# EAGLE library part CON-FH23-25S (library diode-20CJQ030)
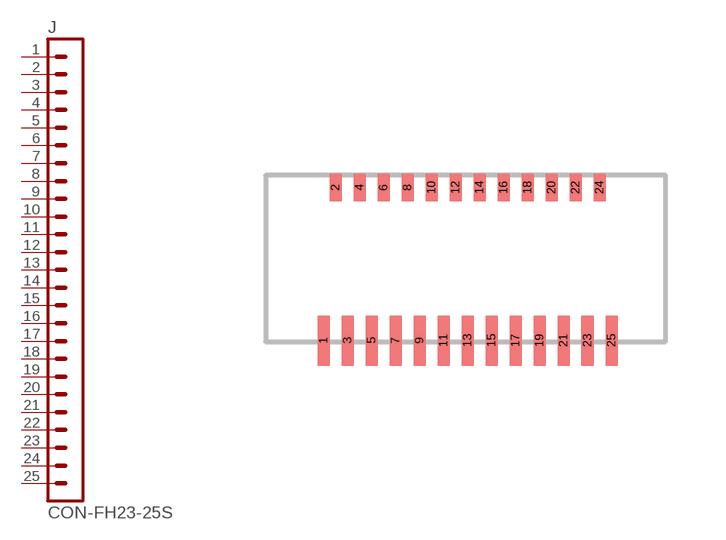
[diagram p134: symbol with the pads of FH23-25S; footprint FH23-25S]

Designator prefix J

## CON-FH23-25S  [FH23-25S]
1  1  pas
2  2  pas
3  3  pas
4  4  pas
5  5  pas
6  6  pas
7  7  pas
8  8  pas
9  9  pas
10  10  pas
11  11  pas
12  12  pas
13  13  pas
14  14  pas
15  15  pas
16  16  pas
17  17  pas
18  18  pas
19  19  pas
20  20  pas
21  21  pas
22  22  pas
23  23  pas
24  24  pas
25  25  pas

## Footprint FH23-25S (pad centres in mm)
0.3mm Contact Pitch, 1.25mm above the board, Flexible Printed Circuit Connectors
smd 0.3 x 1.25: 1 0,0.625; 3 0.6,0.625; 5 1.2,0.625; 7 1.8,0.625; 9 2.4,0.625; 11 3,0.625; 13 3.6,0.625; 15 4.2,0.625; 17 4.8,0.625; 19 5.4,0.625; 21 6,0.625; 23 6.6,0.625; 25 7.2,0.625
smd 0.3 x 0.7: 2 0.3,4.45; 4 0.9,4.45; 6 1.5,4.45; 8 2.1,4.45; 10 2.7,4.45; 12 3.3,4.45; 14 3.9,4.45; 16 4.5,4.45; 18 5.1,4.45; 20 5.7,4.45; 22 6.3,4.45; 24 6.9,4.45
